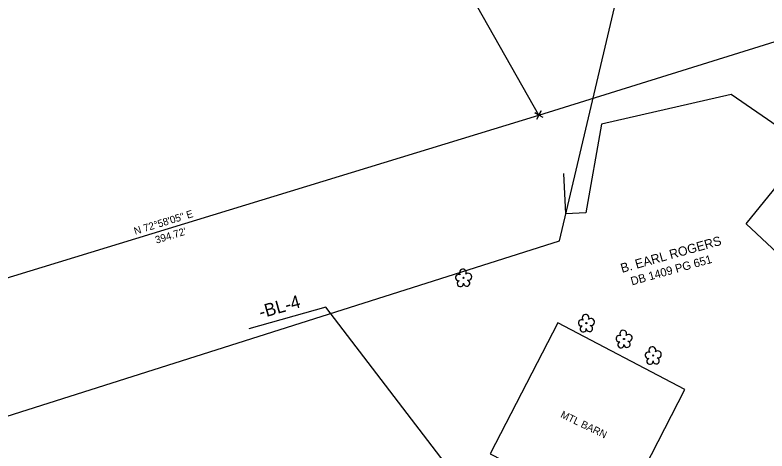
# Model space of a CAD drawing. Extents: x 1316460 to 1321645, y 684173 to 687077.
# Drawn here: x 1318718.2 to 1319126.3, y 685489.6 to 685726.2 of the extents above; entities that cross this region are included whole.
import ezdxf

# ---------------------------------------------------------------- set-up
doc = ezdxf.new("R2010")
doc.units = 0
for name, color, linetype in [('Exist Building', 7, 'Continuous'), ('Exist Building Text', 7, 'Continuous'), ('Exist Horizontal Baseline Alignment Station Label', 7, 'Continuous'), ('Exist Hydrographic Confluence Cogo Description', 7, 'Continuous'), ('Exist Hydrographic Water Surface Cogo Number', 7, 'Continuous'), ('Exist Property Corner CELL', 7, 'Continuous'), ('Exist Property Deed Book Text', 7, 'Continuous'), ('Exist Property Line', 7, 'Continuous'), ('Exist Property Line Text', 7, 'Continuous'), ('Exist Property Owner Text', 7, 'Continuous'), ('Exist Vegetation Woods Line', 7, 'Continuous'), ('Old_Level_59', 7, 'Continuous')]:
    doc.layers.add(name, color=color, linetype=linetype)

# ---------------------------------------------------------------- blocks, each defined once
blk = doc.blocks.new('EXIST VEGETATION TREE')
at = {"layer": 'Exist Hydrographic Confluence Cogo Description'}
blk.add_line((0, 0), (0, 0), dxfattribs=at)
blk.add_circle((0, 0), 0.00652, dxfattribs=at)
for centre, radius, start, end in [((-0.0077, 0.0575), 0.0371, 330.16508, 219.71335), ((-0.0521, 0.0031), 0.0345, 62.66361, 279.3457), ((0.051, 0.0118), 0.038, 257.1011, 134.19993), ((-0.0341, -0.0624), 0.0338, 111.56708, 6.23104), ((0.0335, -0.058), 0.034, 181.28216, 74.55999)]:
    blk.add_arc(centre, radius, start, end, dxfattribs=at)

msp = doc.modelspace()

# ---------------------------------------------------------------- linework, layer by layer
at = {"layer": 'Exist Building'}
msp.add_lwpolyline([(1319012.87, 685559.22), (1318976.15, 685487.96), (1319045.56, 685452.35), (1319081.8, 685522.94)], close=True, dxfattribs=at)
at = {"layer": 'Exist Horizontal Baseline Alignment Station Label'}
for p, q in [((1318886.95, 685567.62), (1318845.17, 685555.85)), ((1318967.64, 685462.27), (1318886.95, 685567.62))]:
    msp.add_line(p, q, dxfattribs=at)
at = {"layer": 'Exist Hydrographic Water Surface Cogo Number'}
for points in [[(1319055.19, 685337.87), (1319087.61, 685357.9), (1319111.37, 685376.19), (1319141.98, 685405.77), (1319163.7, 685432.36), (1319194.31, 685473.2), (1319218.75, 685514.19), (1319240.59, 685549.48), (1319272.58, 685605.07), (1319285.11, 685625.97)], [(1319062.61, 685318.94), (1319095.65, 685339.51), (1319123.83, 685361.21), (1319155.56, 685391.6), (1319180.39, 685419.44), (1319210.73, 685463.75), (1319236.48, 685503.5), (1319257.11, 685540.59), (1319287.5, 685596.76)]]:
    msp.add_spline(points, degree=3, dxfattribs=at)
at = {"layer": 'Exist Property Corner CELL'}
msp.add_line((1319002.51, 685671.94), (1319002.51, 685671.94), dxfattribs=at)
msp.add_lwpolyline([(1319001.34, 685669.73), (1319003.68, 685674.15), (1319002.51, 685671.94), (1319000.3, 685673.11), (1319004.72, 685670.77)], dxfattribs=at)
at = {"layer": 'Exist Property Line'}
for p, q in [((1319002.51, 685671.94), (1318899.71, 685853.45)), ((1319002.51, 685671.94), (1319356.21, 685782.18)), ((1318625.1, 685556.32), (1319002.51, 685671.94))]:
    msp.add_line(p, q, dxfattribs=at)
at = {"layer": 'Exist Vegetation Woods Line'}
msp.add_lwpolyline([(1319160.36, 685570.48), (1319115.06, 685612.94), (1319148.78, 685654.33), (1319106.92, 685683.06), (1319036.51, 685666.96), (1319027.97, 685618.93), (1319017.21, 685618.34), (1319016.02, 685640.13)], dxfattribs=at)
at = {"layer": 'Old_Level_59'}
msp.add_lwpolyline([(1318697.3, 685264.68), (1318675.61, 685496.37), (1319013.72, 685603.72), (1319178.5, 686302.95), (1319290.7, 686462.26), (1319434.76, 686395.34), (1319426.96, 685366.75), (1319230.41, 685144.48), (1318730.33, 685054.78)], close=True, dxfattribs=at)

# ---------------------------------------------------------------- block references
at = {"layer": 'Exist Hydrographic Confluence Cogo Description', "xscale": 50, "yscale": 50}
for p in [(1318961.64, 685583.57), (1319028.29, 685558.97), (1319048.71, 685550.37), (1319064.53, 685541.4)]:
    msp.add_blockref('EXIST VEGETATION TREE', p, dxfattribs=at)

# ---------------------------------------------------------------- texts
at = {"layer": 'Exist Building Text'}
msp.add_text('MTL BARN', height=4, rotation=334.3119, dxfattribs=at).set_placement((1319013.9, 685508))
at = {"layer": 'Exist Horizontal Baseline Alignment Station Label'}
msp.add_text('-BL-4', height=7, rotation=15.7349, dxfattribs=at).set_placement((1318851.63, 685561.44))
at = {"layer": 'Exist Property Deed Book Text'}
msp.add_text('DB 1409 PG 651', height=4.5, rotation=15.7349, dxfattribs=at).set_placement((1319053.05, 685579.42))
at = {"layer": 'Exist Property Line Text'}
for s, p in [('N 72%%D58\'05" E', (1318783.4, 685606.91)), ("394.72'", (1318794.92, 685602.07))]:
    msp.add_text(s, height=4, rotation=17.0319, dxfattribs=at).set_placement(p)
at = {"layer": 'Exist Property Owner Text'}
msp.add_text('B. EARL ROGERS', height=5, rotation=15.7349, dxfattribs=at).set_placement((1319047.67, 685586.23))

doc.saveas('drawing.dxf')
